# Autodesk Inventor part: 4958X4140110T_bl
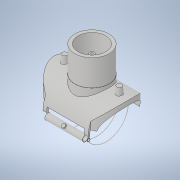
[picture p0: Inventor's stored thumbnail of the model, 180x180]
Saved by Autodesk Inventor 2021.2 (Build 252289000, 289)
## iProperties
Created: 2020-06
Part Number: 4958X4140110T_bl
Material: Generic
Description: Plasson Branch Saddle 140x110
Document SubType Name: Modeling
Designer: KIM
Density: 1 g/cm^3
Appearance: Default
Author: KIM
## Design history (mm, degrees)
derived "4958X4.ipt"
feature "Solid1::4958X4.ipt" dims "ScaleForDerivedMember" = 10
tag "TaggingFeature1"
body "Solid1"
other parameters: "d0" = 242 [user parameter], "d3" = 169.4 [user parameter], "d4" = 109 [user parameter], "d7" = 89 [user parameter], "d9" = 84 [user parameter], "d10" = 0.5 [user parameter], "d11" = 1 [user parameter], "d12" = 27.25 [user parameter], "d13" = 16 [user parameter], "d14" = 8 [user parameter], "d16" = 10 deg [user parameter], "d17" = 10 deg [user parameter], "d19" = 0 [user parameter], "d23" = 0 [user parameter], "d26" = 0 [user parameter], "d27" = 145.2 [user parameter], "d28" = 0 [user parameter], "d29" = 121 [user parameter], "d30" = 0 [user parameter], "d31" = 1 [user parameter], "d32" = 1 [user parameter], "d33" = 19.2 [user parameter], "d34" = 9.6 [user parameter], "d35" = 45 deg [user parameter], "d36" = 121 [user parameter], "d37" = 0 [user parameter], "d38" = 5 [user parameter], "d39" = 85 deg [user parameter], "d40" = 27.25 [user parameter], "d41" = 16 [user parameter], "d42" = 88 [user parameter], "d49" = 3 [user parameter], "d50" = 6 [user parameter], "d51" = 5 [user parameter], "d54" = 0 [user parameter], "d57" = 35 deg [user parameter], "d60" = 15.125 [user parameter], "d61" = 1 [user parameter], "d62" = 90 deg [user parameter], "d63" = 2 [user parameter], "d64" = 0 [user parameter], "d65" = 0 [user parameter], "d68" = 30.25 [user parameter], "d70" = 0.57711 [user parameter], "d71" = 10 deg [user parameter], "d73" = 5.145 [user parameter], "B" = 189 [user parameter], "L" = 242 [user parameter], "LS" = 84 [user parameter], "H1" = 109 [user parameter], "Dt" = 16 [user parameter], "di" = 89 [user parameter], "d72" = 14.7 [user parameter]
